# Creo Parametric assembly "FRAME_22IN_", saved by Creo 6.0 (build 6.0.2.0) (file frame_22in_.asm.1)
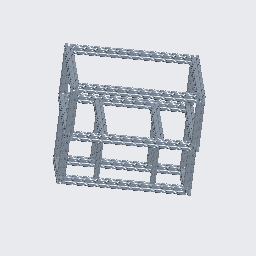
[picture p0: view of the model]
Units: Inch lbm Second (Pro/E Default); INCH, POUND, SECS

Created from: INLBS_ASM_DESIGN.ASM

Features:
  1. datum plane "ASM_RIGHT"
  2. datum plane "ASM_TOP"
  3. datum plane "ASM_FRONT"
  4. coordinate system
  5. component "8020_12IN_", "8020_12IN.PRT"
  6. component "8020_22IN_", "8020_22IN.PRT"
  7. component "8020_22IN_", "8020_22IN.PRT"
  8. component "8020_12IN_", "8020_12IN.PRT"
  9. component "8020_9IN_", "8020_9IN.PRT"
  10. component "8020_9IN_", "8020_9IN.PRT"
  11. component "8020_9IN_", "8020_9IN.PRT"
  12. component "8020_9IN_", "8020_9IN.PRT"
  13. component "8020_22IN_", "8020_22IN.PRT"
  14. component "8020_22IN_", "8020_22IN.PRT"
  15. component "8020_22IN_", "8020_22IN.PRT"
  16. component "8020_22IN_", "8020_22IN.PRT"
  17. component "8020_19IN_", "8020_19IN.PRT"
  18. component "8020_19IN_", "8020_19IN.PRT"
  19. component "8020_8IN_", "8020_8IN.PRT"
  20. component "8020_8IN_", "8020_8IN.PRT"
  21. component "8020_8IN_", "8020_8IN.PRT"
  22. component "8020_8IN_", "8020_8IN.PRT"
  23. component "8020_22IN_", "8020_22IN.PRT"
  24. component "8020_22IN_", "8020_22IN.PRT"
  25. component "8020_22IN_", "8020_22IN.PRT"
  26. component "8020_22IN_", "8020_22IN.PRT"
  27. component "8020_1X9IN_", "8020_1X9IN.PRT"
  28. component "8020_1X9IN_", "8020_1X9IN.PRT"
  29. component "8020_1X9IN_", "8020_1X9IN.PRT"
  30. component "8020_1X9IN_", "8020_1X9IN.PRT"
